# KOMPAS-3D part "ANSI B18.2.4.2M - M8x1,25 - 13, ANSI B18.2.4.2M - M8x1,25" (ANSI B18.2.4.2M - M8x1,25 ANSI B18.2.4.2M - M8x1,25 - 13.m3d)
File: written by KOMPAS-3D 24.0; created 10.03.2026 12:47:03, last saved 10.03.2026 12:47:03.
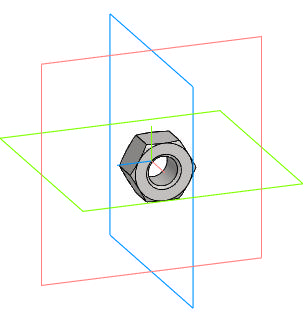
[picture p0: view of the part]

Document properties: Автор: R2D2; Полное имя файла: E:\Работа\Зайцев\BV3232P(4pc)-FP-3WL-F-ISO-H Кран шаровой DN.ru Ду15-100 Ру16\DN50\исходные материалы\ANSI B18.2.4.2M - M8x1,25 ANSI B18.2.4.2M - M8x1,25 - 13.m3d

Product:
- Body: Solid1  | qty 1
- Part/product: ANSI B18.2.4.2M - M8x1,25 - 13  | designation ANSI B18.2.4.2M - M8x1,25
    Комментарий: Типы метрических   шестигранных гаек   2
    additional columns: Сталь, мягкая

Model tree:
1. Solid1  (labels: Solid1)

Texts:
  ANSI B18.2.4.2M - M8x1,25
